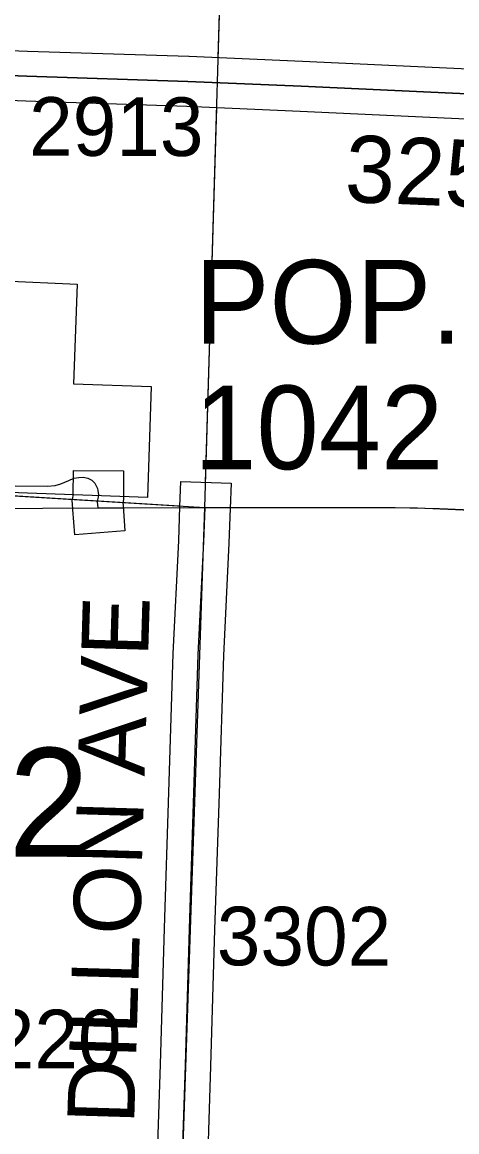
# Model space of a CAD drawing. Extents: x -157.2 to -99.3, y 12.2 to 46.2.
# Drawn here: x -139.294 to -138.775, y 17.233 to 18.559 of the extents above; entities that cross this region are included whole.
import ezdxf

# ---------------------------------------------------------------- set-up
doc = ezdxf.new("R2010")
doc.units = 0
for name, color, linetype in [('tdCoCityStreetMajor', 7, 'Continuous'), ('tdCoCorpBndry', 7, 'Continuous'), ('tdCoCorpPopTxt', 7, 'Continuous'), ('tdCoPriCL', 7, 'Continuous'), ('tdCoPriNonDiv', 7, 'Continuous'), ('tdCoPriNonDivCL', 7, 'Continuous'), ('tdCoSecRdNmbr', 7, 'Continuous'), ('tdCoSecRdTxt', 7, 'Continuous'), ('tdCoSecRteBand', 7, 'Continuous'), ('tdCoSecRteCL', 7, 'Continuous'), ('tdCoSectLine', 7, 'Continuous'), ('tdCoSectLinePart', 7, 'Continuous'), ('tdCoSectNmbr', 7, 'Continuous'), ('tdCoSurfAsphalt', 7, 'Continuous'), ('tdCoSurfGravel', 7, 'Continuous')]:
    doc.layers.add(name, color=color, linetype=linetype)

msp = doc.modelspace()

# ---------------------------------------------------------------- linework, layer by layer
at = {"layer": 'tdCoCityStreetMajor'}
msp.add_lwpolyline([(-139.57, 18.0099), (-139.5422, 18.0084), (-139.5061, 18.0075), (-139.4947, 18.0072), (-139.4444, 18.0067), (-139.3547, 18.0059), (-139.3019, 18.0053), (-139.2635, 18.0048), (-139.2544, 18.0059), (-139.2477, 18.0079), (-139.2381, 18.0118), (-139.2319, 18.0144), (-139.2262, 18.0154), (-139.2207, 18.0157), (-139.2153, 18.0144), (-139.2106, 18.0121), (-139.207, 18.0085), (-139.2059, 18.0063), (-139.2039, 18.0022), (-139.2034, 17.9996), (-139.2027, 17.9947), (-139.2027, 17.9941), (-139.2027, 17.9935)], dxfattribs=at)
at = {"layer": 'tdCoCorpBndry'}
msp.add_lwpolyline([(-139.316, 18.2503), (-139.228, 18.2464), (-139.2322, 18.1272), (-139.1395, 18.1239), (-139.1442, 17.9914), (-139.4086, 18.0009)], dxfattribs=at)
at = {"layer": 'tdCoPriCL'}
msp.add_lwpolyline([(-139.4704, 17.9783), (-139.2694, 17.9788), (-139.2035, 17.9791), (-139.0757, 17.9795), (-139.0563, 17.9796), (-138.8482, 17.9796), (-138.7952, 17.9783), (-138.701, 17.9744)], dxfattribs=at)
at = {"layer": 'tdCoPriNonDiv'}
msp.add_lwpolyline([(-140.3722, 18.019), (-140.2521, 18.0077), (-140.1707, 18), (-140.0139, 17.9855), (-139.9668, 17.9816), (-139.9399, 17.9796), (-139.9064, 17.9788), (-139.8474, 17.9776), (-139.78, 17.9779), (-139.6552, 17.9785), (-139.6381, 17.9786), (-139.4704, 17.9783), (-139.2694, 17.9788), (-139.0757, 17.9795), (-139.0563, 17.9796), (-138.8482, 17.9796), (-138.7952, 17.9783), (-138.701, 17.9744), (-138.6575, 17.9724), (-138.4432, 17.9628), (-138.2124, 17.9525), (-138.0085, 17.9436), (-137.7922, 17.9335), (-137.5683, 17.9224)], dxfattribs=at)
at = {"layer": 'tdCoPriNonDivCL'}
msp.add_lwpolyline([(-139.4704, 17.9783), (-139.2694, 17.9788), (-139.2035, 17.9791), (-139.0757, 17.9795), (-139.0563, 17.9796), (-138.8482, 17.9796), (-138.7952, 17.9783), (-138.701, 17.9744)], dxfattribs=at)
msp.add_lwpolyline([(-139.4704, 17.9783), (-139.2694, 17.9788), (-139.2035, 17.9791), (-139.0757, 17.9795), (-139.0563, 17.9796), (-138.8482, 17.9796), (-138.7952, 17.9783), (-138.701, 17.9744)], dxfattribs=at)
at = {"layer": 'tdCoSecRteBand'}
for points in [[(-138.7382, 18.4424), (-138.9618, 18.4528), (-139.0969, 18.4586), (-139.2893, 18.4648), (-139.2894, 18.4648), (-139.2895, 18.4648), (-139.3102, 18.4656), (-139.3396, 18.4667), (-139.4068, 18.4692), (-139.5585, 18.4747), (-139.5882, 18.4758), (-139.5874, 18.5055), (-139.5855, 18.5737)], [(-139.5255, 18.5721), (-139.5266, 18.5336), (-139.4046, 18.5292), (-139.4046, 18.5292), (-139.4046, 18.5292), (-139.3374, 18.5267), (-139.3079, 18.5255), (-139.2873, 18.5248), (-139.0948, 18.5186), (-139.0946, 18.5186), (-139.0944, 18.5186), (-138.9591, 18.5127), (-138.9591, 18.5127), (-138.959, 18.5127), (-138.7354, 18.5024)], [(-139.2308, 17.9469), (-139.233, 17.9769), (-139.2335, 17.984), (-139.2338, 17.9874), (-139.2332, 17.9909), (-139.2328, 17.9935), (-139.2327, 17.9942), (-139.2325, 18.0237), (-139.1725, 18.0233), (-139.1727, 17.9933), (-139.1727, 17.9921), (-139.1727, 17.992), (-139.1727, 17.9919), (-139.1727, 17.9911), (-139.1728, 17.989), (-139.1731, 17.9869), (-139.1734, 17.9849), (-139.1732, 17.9813), (-139.171, 17.9514), (-139.2308, 17.9469)], [(-139.1341, 17.1474), (-139.1286, 17.3138), (-139.1239, 17.4768), (-139.1239, 17.4768), (-139.1239, 17.4769), (-139.1185, 17.6394), (-139.1133, 17.8046), (-139.1133, 17.8048), (-139.1133, 17.8051), (-139.1068, 17.9396), (-139.1053, 17.9806), (-139.1042, 18.0106), (-139.0443, 18.0084), (-139.0454, 17.9784), (-139.0468, 17.9372), (-139.0468, 17.9371), (-139.0469, 17.9369), (-139.0534, 17.8024), (-139.0585, 17.6375), (-139.0585, 17.6374), (-139.0586, 17.6374), (-139.064, 17.475), (-139.0687, 17.312), (-139.0687, 17.312), (-139.0687, 17.3119), (-139.0741, 17.1455)]]:
    msp.add_lwpolyline(points, dxfattribs=at)
at = {"layer": 'tdCoSecRteCL'}
for points in [[(-138.0691, 18.4398), (-138.1661, 18.4443), (-138.3617, 18.4541), (-138.4758, 18.4601), (-138.6265, 18.4672), (-138.7368, 18.4724), (-138.9604, 18.4828), (-139.0957, 18.4886), (-139.2883, 18.4948), (-139.309, 18.4956), (-139.3385, 18.4967), (-139.4057, 18.4992), (-139.5574, 18.5047), (-139.5555, 18.5729), (-139.554, 18.6279), (-139.5507, 18.7578), (-139.5498, 18.7949), (-139.5449, 18.9653), (-139.544, 18.9997)], [(-139.2031, 17.9791), (-139.2036, 17.9862), (-139.2032, 17.9887), (-139.2027, 17.9916), (-139.2027, 17.9924), (-139.2027, 17.9935)], [(-139.1087, 16.9941), (-139.1068, 17.0517), (-139.1041, 17.1464), (-139.0986, 17.3129), (-139.094, 17.4759), (-139.0885, 17.6384), (-139.0834, 17.8036), (-139.0768, 17.9383), (-139.0753, 17.9795)]]:
    msp.add_lwpolyline(points, dxfattribs=at)
at = {"layer": 'tdCoSectLine'}
for points in [[(-139.0757, 17.9795), (-139.0457, 18.9836)], [(-140.0736, 18.0295), (-139.5704, 18.0099), (-139.0757, 17.9795)], [(-139.109, 16.9941), (-139.0757, 17.9795)], [(-139.0757, 17.9795), (-138.8217, 17.979), (-138.0858, 17.9469)]]:
    msp.add_lwpolyline(points, dxfattribs=at)
at = {"layer": 'tdCoSectLinePart'}
for points in [[(-139.0597, 18.517), (-139.0466, 18.9535)], [(-139.0748, 18.0095), (-139.0614, 18.4571)], [(-139.4609, 18.0032), (-139.1059, 17.9814)], [(-139.046, 17.9794), (-138.8217, 17.979), (-138.1162, 17.9483)]]:
    msp.add_lwpolyline(points, dxfattribs=at)
at = {"layer": 'tdCoSurfAsphalt'}
msp.add_lwpolyline([(-139.2031, 17.9791), (-139.2036, 17.9862), (-139.2032, 17.9887), (-139.2027, 17.9916), (-139.2027, 17.9924), (-139.2027, 17.9935)], dxfattribs=at)
at = {"layer": 'tdCoSurfGravel'}
for points in [[(-139.309, 18.4956), (-139.2883, 18.4948), (-139.0957, 18.4886), (-138.9604, 18.4828), (-138.7368, 18.4724), (-138.6265, 18.4672), (-138.4758, 18.4601), (-138.3617, 18.4541), (-138.1661, 18.4443), (-138.0691, 18.4398)], [(-139.1087, 16.9941), (-139.1068, 17.0517), (-139.1041, 17.1464), (-139.0986, 17.3129), (-139.094, 17.4759), (-139.0885, 17.6384), (-139.0834, 17.8036), (-139.0768, 17.9383), (-139.0753, 17.9795)]]:
    msp.add_lwpolyline(points, dxfattribs=at)

# ---------------------------------------------------------------- texts
at = {"layer": 'tdCoCorpPopTxt'}
for s, p in [('POP.', (-139.0876, 18.1752)), ('1042', (-139.0883, 18.0252))]:
    msp.add_text(s, height=0.1, dxfattribs=at).set_placement(p)
at = {"layer": 'tdCoSecRdNmbr'}
for s, rotation, p in [('2913', 359.8946, (-139.2855, 18.3998)), ('3302', 359.8948, (-139.0613, 17.4324)), ('3220', 359.8946, (-139.3833, 17.3095))]:
    msp.add_text(s, height=0.07, rotation=rotation, dxfattribs=at).set_placement(p)
at = {"layer": 'tdCoSecRdTxt'}
for s, rotation, p in [('325TH ST', 357.6787, (-138.9092, 18.3447)), ('DILLON AVE', 88.2879, (-139.16, 17.242))]:
    msp.add_text(s, height=0.08, rotation=rotation, dxfattribs=at).set_placement(p)
at = {"layer": 'tdCoSectNmbr'}
msp.add_text('32', height=0.13, rotation=359.8945, dxfattribs=at).set_placement((-139.4067, 17.5623))

doc.saveas('drawing.dxf')
